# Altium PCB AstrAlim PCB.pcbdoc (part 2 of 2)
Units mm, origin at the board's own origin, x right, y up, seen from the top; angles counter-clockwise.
Board outline 123.28 x 79.48 mm, 4 copper layers (Top Layer, Inner1, Inner2, Bottom Layer); 156 components, 74 nets, 482 pads, 222 vias.
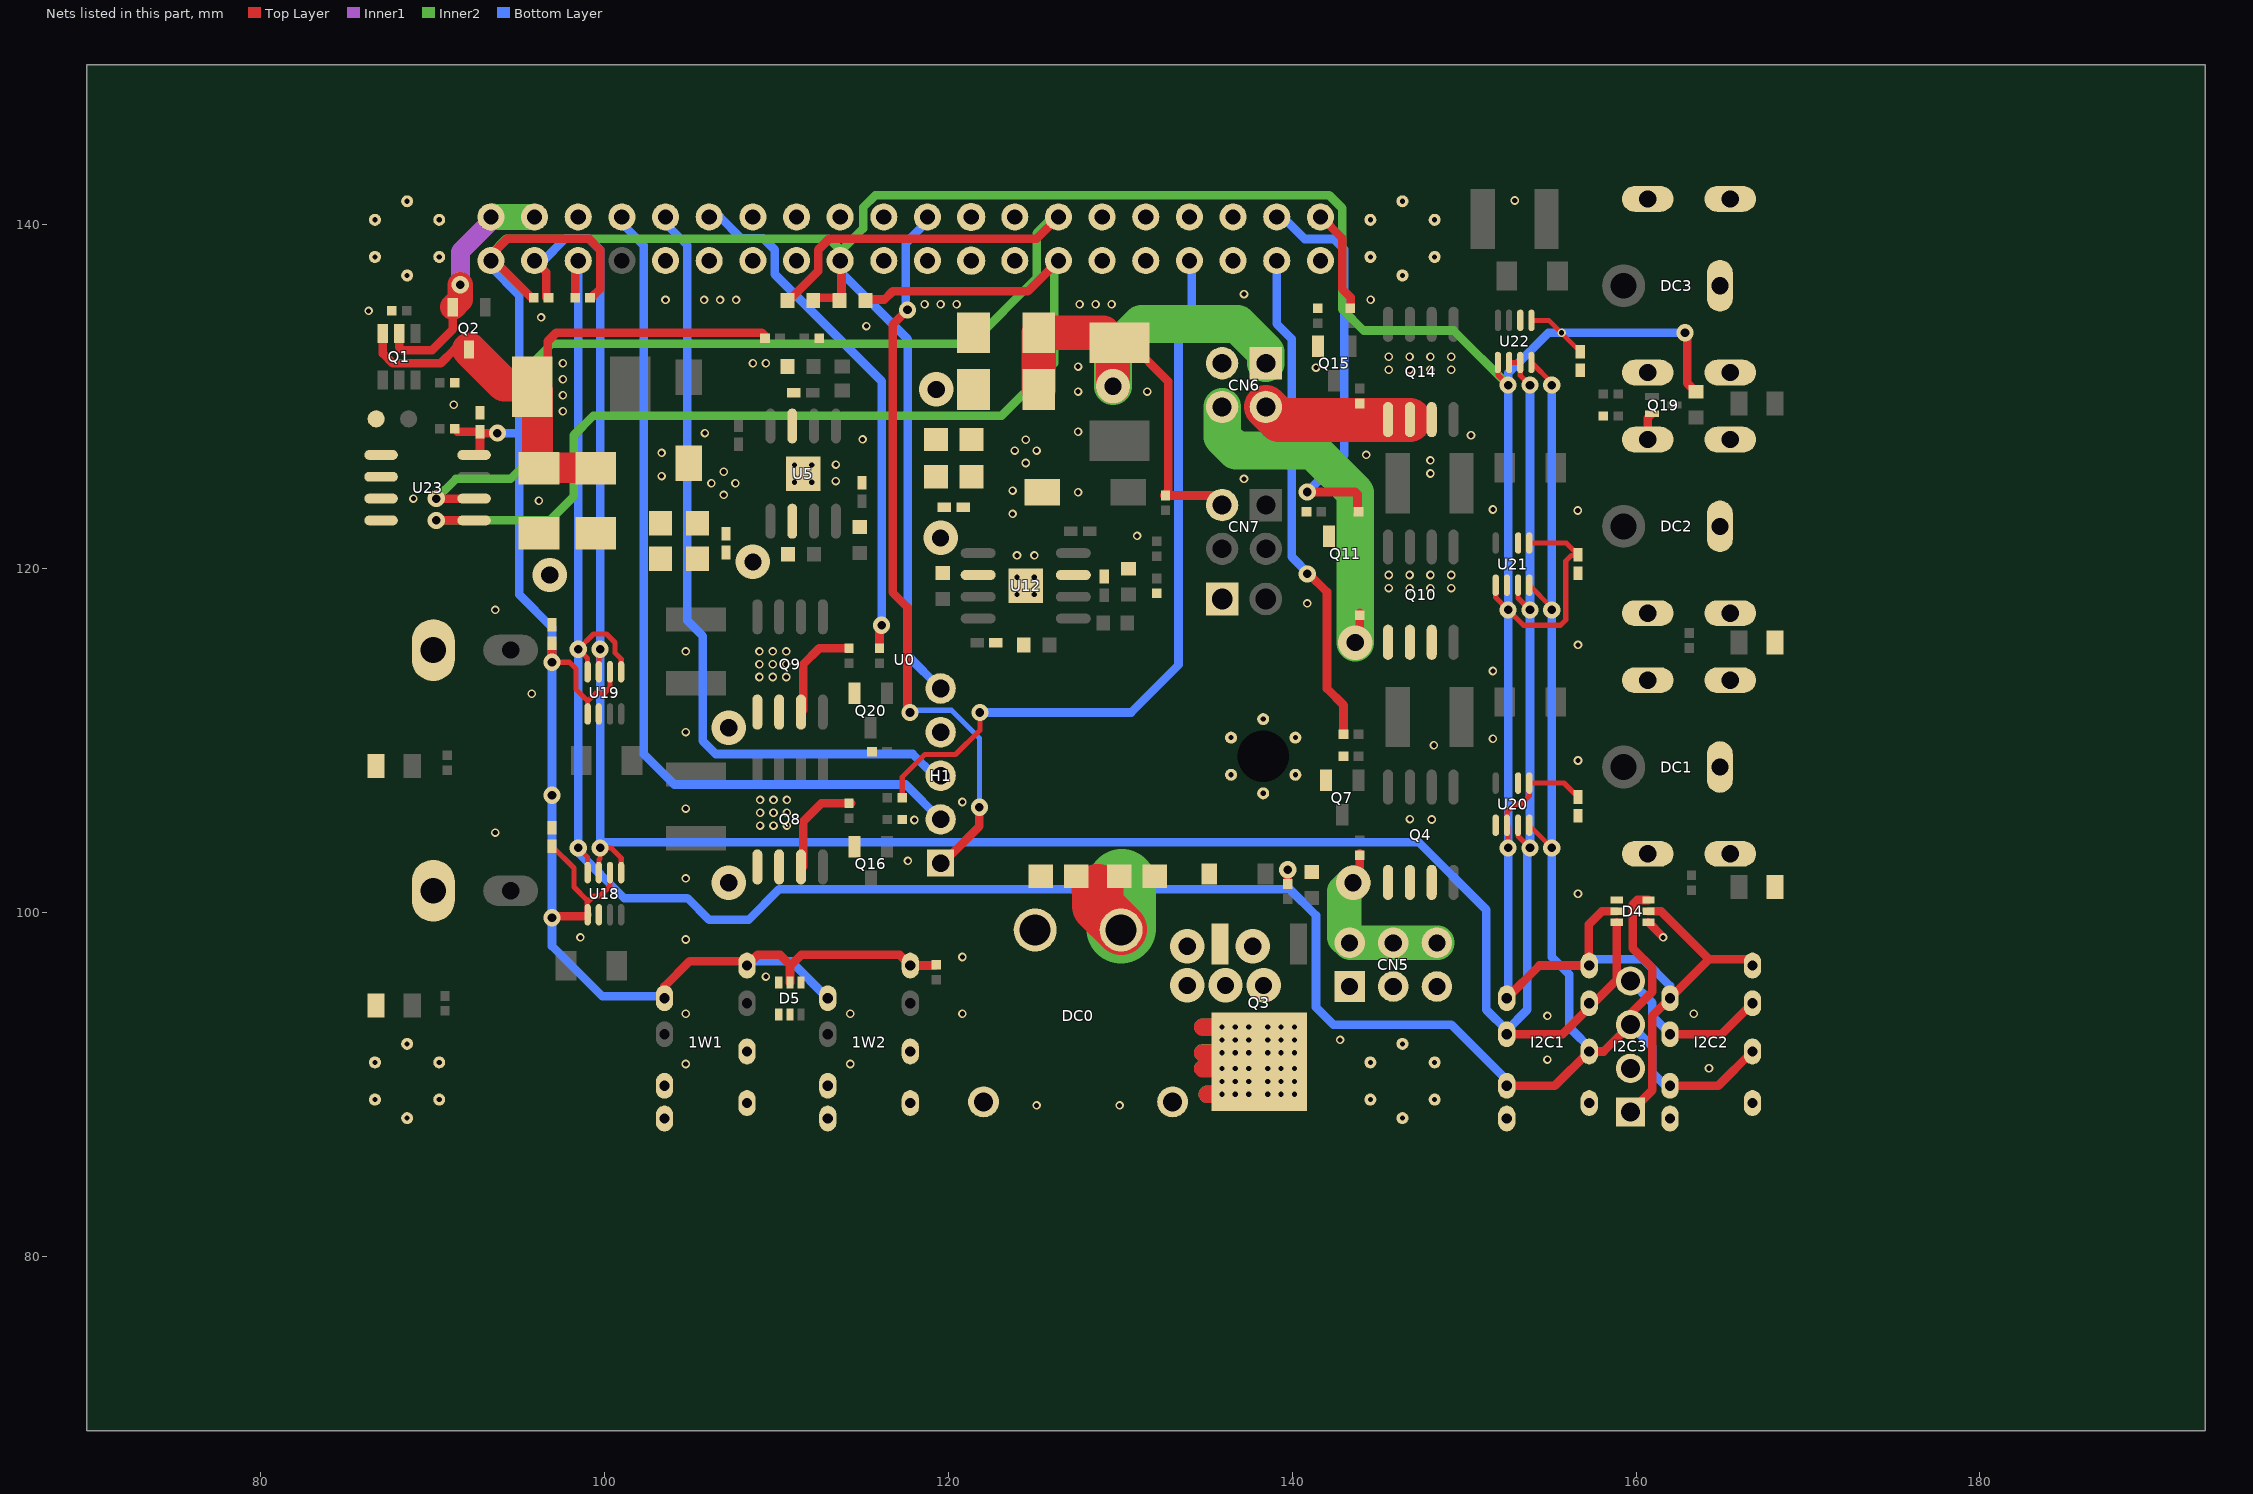
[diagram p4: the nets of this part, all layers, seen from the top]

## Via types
v1: diameter 0.5, hole 0.3, Top Layer to Bottom Layer, 164 vias
v2: diameter 1, hole 0.5, Top Layer to Bottom Layer, 30 vias
v3: diameter 2, hole 1, Top Layer to Bottom Layer, 14 vias
v4: diameter 0.61, hole 0.305, Top Layer to Bottom Layer, 8 vias
v5: diameter 0.8, hole 0.4, Top Layer to Bottom Layer, 6 vias

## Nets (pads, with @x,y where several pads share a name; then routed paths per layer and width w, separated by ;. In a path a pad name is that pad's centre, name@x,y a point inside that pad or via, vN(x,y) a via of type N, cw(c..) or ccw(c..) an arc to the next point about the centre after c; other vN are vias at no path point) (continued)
+3.3V: 1W1.4 1W1.8 1W2.4 1W2.8 C16.1 C19.1 C20.1 C30.1 C32.1 C38.2 D4.2 D4.5 D5.5 H1.5 I2C1.4 I2C1.8 I2C2.4 I2C2.8 I2C3.1 R6.2 R7.2 R19.2 R88.1 R89.2 R90.2 R91.2 U0.1 U0.17 U18.2 U18.5 U19.2 U19.5 U20.2 U20.5 U21.1 U21.5 U22.1 U22.5 U23.8 | length 324.2
  Top Layer w0.3: C19.1@96.933,103.849 98.203,102.579 98.203,101.473 98.965,100.711 98.965,100.584 ; v2(96.933,114.554) 97.949,114.554 98.33,114.173 98.33,112.985 99.006,112.309 ; U18.5@98.965,99.825 98.965,100.584 ; U19.5@99.006,111.55 99.006,112.309 ; U18.2@100.306,102.318 100.306,101.544 99.727,100.965 99.346,100.965 98.965,100.584 ; U19.2@100.306,114.002 100.306,113.101 99.981,112.776 99.473,112.776 99.006,112.309 ; U21.1@151.838,119.043 151.838,118.323 v2(152.559,117.602) 153.448,116.713 155.607,116.713 155.907,117.013 155.907,120.442 156.242,120.777 156.586,120.777 C30.1@156.623,120.814 155.942,121.495 U21.5@153.788,121.495 ; U22.1@151.965,131.997 151.965,131.277 v2(152.559,130.683) ; v2(152.559,103.759) 152.559,105.002 U20.2@152.488,105.073 152.488,105.847 152.94,106.299 153.321,106.299 153.788,106.766 U20.5@153.788,107.525 155.815,107.525 C16.1@156.623,106.717 ; U22.5@153.915,134.449 154.926,134.449 C32.1@156.75,132.625
  Top Layer w0.5: R91.2@91.27,128.143 91.434,127.979 C38.2@92.742,127.979 ; U23.8@92.145,126.619 92.488,126.619 92.742,126.873 C38.2@92.742,127.979 ; v2(93.758,127.889) 92.832,127.889 C38.2@92.742,127.979 ; R6.2@95.738,135.763 93.579,137.922 U0.1@93.377,137.922 93.377,138.242 94.327,139.192 99.084,139.192 99.727,138.549 99.727,136.271 99.219,135.763 R7.2@99.144,135.763 ; v2(96.933,99.695) 97.018,99.78 98.965,99.78 98.965,99.825 U18.5@99.006,99.866 ; v2(96.933,114.554) C20.1@96.933,115.66 ; 1W1.8@103.477,95.012 103.477,95.698 104.934,97.155 108.034,97.155 1W1.4@108.277,96.912 108.901,97.536 110.194,97.536 110.818,96.912 ; D5.5@110.776,95.916 110.776,96.87 110.818,96.912 ; R90.2@112.479,135.763 113.772,135.763 113.772,137.847 U0.17@113.697,137.922 ; R19.2@119.285,96.953 119.244,96.912 1W2.4@117.777,96.912 117.153,97.536 111.442,97.536 110.818,96.912 ; I2C1.8@152.477,95.012 154.377,96.912 I2C1.4@157.277,96.912 157.258,96.931 157.258,99.314 158.02,100.076 D4.5@158.878,100.076 ; I2C3.1@159.671,88.392 160.941,89.662 160.941,93.976 I2C2.8@161.977,95.012 164.247,97.282 ; D4.2@160.718,100.076 161.453,100.076 164.247,97.282 ; v2(162.846,133.731) 162.981,133.596 162.981,130.793 R88.1@163.481,130.293 ; I2C2.4@166.777,96.912 166.407,97.282 164.247,97.282
  Inner2 w0.5: U0.1@93.377,137.922 93.377,138.303 94.266,139.192 113.062,139.192 113.697,138.557 U0.17@113.697,138.459 ; U0.17@113.697,137.922 U0.17@113.697,138.459 ; v2(152.559,130.683) 149.384,133.858 144.148,133.858 142.907,135.099 142.907,140.97 142.145,141.732 115.75,141.732 115.033,141.015 115.033,139.794 U0.17@113.697,138.459
  Bottom Layer w0.5: U0.1@93.377,137.922 93.377,137.545 95.028,135.894 95.028,127.909 ; v2(93.758,127.889) 95.008,127.889 95.028,127.909 ; 1W1.8@103.423,95.517 103.423,95.133 99.844,95.133 96.933,98.044 v2(96.933,99.695) v2(96.933,106.823) v2(96.933,114.554) 96.933,116.586 95.028,118.491 95.028,127.909 ; 1W1.4@108.277,96.912 108.52,97.155 110.834,97.155 1W2.8@112.977,95.012 ; U0.17@113.697,137.922 113.697,137.287 117.634,133.35 117.634,114.935 H1.5@119.539,113.03 ; I2C1.8@152.559,95.43 v2(152.559,103.759) v2(152.559,117.602) v2(152.559,130.683) 152.559,131.39 154.9,133.731 v1(155.667,133.731) v2(162.846,133.731) ; I2C1.4@157.277,96.912 157.647,97.282 160.414,97.282 161.977,95.719 I2C2.8@161.977,95.012
+5V_A: C10.1 C11.1 Q1.6 Q2.3 R14.2 U6.2 | length 34.4
  Top Layer w0.5: Q1.6@87.093,133.684 87.093,132.522 87.662,131.953 90.456,131.953 91.253,132.75 Q2.3@92.107,132.75 ; U6.2@95.79,130.714 96.679,131.603 96.679,133.231 97.179,133.731 109.137,133.731 109.327,133.541 R14.2@109.327,133.413
  Top Layer w1.8: U6.2@95.79,130.714 96.1,130.404 96.1,125.902 96.129,125.873 C11.1@98.382,125.873
  Top Layer w2: Q2.3@92.107,132.75 94.143,130.714 U6.2@95.79,130.714
+5V_PI: Q1.5 Q2.2 U0.2 U0.4 | length 14.6
  Top Layer w0.5: Q1.5@88.043,133.684 88.043,132.88 88.208,132.715 89.948,132.715 91.157,133.924 Q2.2@91.157,135.22
  Top Layer w1.5: Q2.2@91.157,135.22 91.599,135.662 v2(91.599,136.525)
  Inner1 w1.1: v2@91.599,136.652 91.599,138.43 93.377,140.208 U0.2@93.377,140.589
  Inner2 w1.3: U0.2@93.504,140.462 U0.2@93.504,140.589
  Inner2 w1.5: U0.2@93.377,140.462 93.504,140.462 U0.4@95.917,140.462
+9V: C26.1 C27.1 CN6.1 CN7.3 R67.2 U13.2 | length 37.7
  Top Layer w0.5: U13.2@129.572,133.152 130.532,133.152 132.787,130.897 132.787,124.5 R67.2@132.545,124.258 ; R67.2@132.62,124.258 135.362,124.258 CN7.3@135.922,123.698
  Top Layer w2: C27.1@125.248,130.429 C26.1@125.248,133.731 128.993,133.731 129.572,133.152 v3(129.572,130.611)
  Inner2 w2.2: v3(129.572,130.611) 129.572,132.588 131.223,134.239 136.811,134.239 138.462,132.588 CN6.1@138.462,131.953
+12V: C5.2 C6.2 C7.2 C21.2 C22.2 C23.2 C34.2 C35.2 CN5.2 CN5.4 CN5.6 CN6.4 DC0.2 Q4.1 Q4.2 Q4.3 Q8.1 Q8.2 Q8.3 Q9.1 Q9.2 Q9.3 Q10.1 Q10.2 Q10.3 R10.2 R17.1 R22.2 R27.2 R30.2 R32.2 R42.2 U5.2 U12.2 | length 50.3
  Top Layer w0.5: Q9.3@111.418,111.654 111.538,111.774 111.538,114.427 112.479,115.368 R30.2@114.205,115.368 ; Q8.3@111.545,102.648 111.545,105.29 112.606,106.351 R27.2@114.332,106.351 ; R17.1@139.732,101.652 v2(139.732,102.489) ; v3(143.542,101.727) 143.923,102.108 R22.2@143.923,103.453 ; v3(143.669,115.697) 143.923,115.951 R42.2@143.923,117.423
  Top Layer w3: 128.667,101.325 128.683,101.31 128.683,100.377 DC0.2@130.04,99.02
  Inner2 w2: v3(143.542,101.727) 143.034,101.219 143.034,98.565 143.367,98.232 CN5.4@145.877,98.232 CN5.6@148.447,98.232
  Inner2 w2.2: CN6.4@135.922,129.413 135.922,127.676 136.725,126.873 141.215,126.873 143.669,124.419 v3(143.669,115.697)
  Inner2 w4: DC0.2@130.04,99.02 130.08,99.06 130.08,101.68
  other v1: 109.036,105.056 109.816,105.056 110.596,105.056 109.036,105.802 109.816,105.802 110.596,105.802 109.036,106.548 109.816,106.548 110.596,106.548 108.998,113.697 109.778,113.697 110.558,113.697 108.998,114.443 109.778,114.443 110.558,114.443 108.998,115.189 109.778,115.189 110.558,115.189
  other v3: 107.22,101.727 107.22,110.744 108.617,120.396 119.539,121.793
GND: 1W1.1 1W1.5 1W2.1 1W2.5 C5.1 C6.1 C7.1 C8.1 C10.2 C11.2 C13.1 C16.2 C19.2 C20.2 C21.1 C22.1 C23.1 C24.1 C26.2 C27.2 C29.1 C30.2 C32.2 C34.1 C35.1 C38.1 CN5.1 CN5.3 CN5.5 CN8.1 D1.1 D2.2 D3.1 D4.1 D4.4 D5.4 DC1.2 DC1.3 DC2.2 DC2.3 DC3.2 DC3.3 GN0.1 H1.4 I2C1.1 I2C1.5 I2C2.1 I2C2.5 I2C3.2 LED1.2 LED2.2 LED4.2 LED5.2 pad.42 pad.44 pad.46 pad.48 pad.50 pad.52 PWM1.1 PWM2.1 Q3.3 Q7.2 Q11.2 Q15.2 Q16.2 Q19.2 Q20.2 R11.1 R12.2 R13.1 R16.1 R18.1 R20.1 R33.1 R34.2 R39.1 R40.1 R48.1 R54.1 R56.1 R59.1 R87.1 U0.6 U0.9 U0.14 U0.20 U0.25 U0.30 U0.34 U0.39 U0.42 U0.44 U0.46 U0.48 U0.50 U0.52 U5.7 U5.9 U12.7 U12.9 U18.6 U19.6 U20.1 U20.6 U21.2 U21.6 U22.6 U23.3 U23.4 | length 2.8
  Top Layer w0.5: DC2.2@160.677,127.512 160.677,128.768 Q19.2@160.926,129.017 ; D4.1@160.718,99.426 161.576,98.568 v1(161.576,98.552)
  other v1: 125.127,88.773 129.953,88.773 164.243,90.932 104.712,91.186 114.283,91.186 154.845,91.44 142.78,92.583 154.845,93.98 104.712,94.107 114.283,94.107 120.809,94.107 163.354,94.107 109.379,96.266 120.809,97.409 104.712,98.425 98.584,98.552 156.623,101.092 104.712,101.981 117.634,102.997 93.631,104.648 118.015,105.378 148.114,105.41 146.844,105.429 104.712,106.045 120.809,106.426 156.623,108.839 148.241,109.728 151.67,110.109 104.712,110.49 95.754,112.725 151.67,114.046 104.712,115.189 156.623,115.57 93.631,117.602 140.875,117.983 145.614,118.872 146.826,118.872 148.033,118.872 149.249,118.872 145.614,119.634 146.826,119.634 148.033,119.634 149.249,119.634 123.984,120.777 125,120.777 130.969,121.91 123.73,123.19 156.613,123.384 151.67,123.444 96.171,123.952 88.869,124.079 106.921,124.292 127.543,124.451 123.73,124.542 106.204,124.968 107.601,124.968 113.443,125.095 137.192,125.222 103.312,125.39 148.033,125.54 106.921,125.644 113.451,126.057 124.492,126.148 148.033,126.302 144.304,126.619 103.312,126.74 123.857,126.873 125.127,126.873 124.492,127.5 115.004,127.524 150.4,127.762 105.823,127.889 127.543,127.971 97.568,129.159 91.218,129.54 97.568,130.09 127.543,130.302 131.564,130.302 97.568,131.022 145.614,131.572 146.826,131.572 148.033,131.572 149.249,131.572 141.383,131.699 127.543,131.76 97.568,131.953 108.617,131.953 109.379,131.953 145.614,132.334 146.826,132.334 148.033,132.334 149.249,132.334 115.221,134.112 96.298,134.62 86.265,135.001 118.608,135.382 119.539,135.382 120.47,135.382 127.625,135.382 128.556,135.382 129.487,135.382 103.537,135.636 105.781,135.636 106.712,135.636 107.643,135.636 144.558,135.651 137.192,135.978 152.94,141.424
  other v3: 133.89,95.758 136.112,95.758 138.335,95.758 133.89,98.034 137.7,98.034 96.806,119.634 119.285,130.429
GND_IN: DC0.1 Q3.2 | length 8.5
  Top Layer w1: 134.778,90.906 Q3.2@135.778,90.906 ; 134.778,91.828 Q3.2@135.778,91.828 ; 134.778,93.319 Q3.2@135.778,93.319 ; 135.032,89.415 Q3.2@136.032,89.415
  Inner2 w1: 134.777,90.916 v1(135.904,90.916) ; 134.777,91.837 v1(135.904,91.837) ; 134.777,93.329 v1(135.904,93.329) ; 135.031,89.424 v1(135.904,89.424) 136.158,89.424
  other v1: 136.684,89.424 137.464,89.424 138.571,89.424 139.351,89.424 140.131,89.424 135.904,90.17 136.684,90.17 137.464,90.17 138.571,90.17 139.351,90.17 140.131,90.17 136.684,90.916 137.464,90.916 138.571,90.916 139.351,90.916 140.131,90.916 136.684,91.837 137.464,91.837 138.571,91.837 139.351,91.837 140.131,91.837 135.904,92.583 136.684,92.583 137.464,92.583 138.571,92.583 139.351,92.583 140.131,92.583 136.684,93.329 137.464,93.329 138.571,93.329 139.351,93.329 140.131,93.329
GPIO13_PWM1: R53.1 U0.33 | length 44.5
  Top Layer w0.3: R53.1@117.305,106.68 117.305,107.875 118.623,109.193 120.415,109.193 121.825,110.603 v2(121.825,111.633)
  Bottom Layer w0.5: v2(121.825,111.633) 130.615,111.633 133.382,114.4 133.382,133.35 134.144,134.112 U0.33@134.144,137.992
GPIO18_PWM0: R55.1 U0.12 | length 30.4
  Top Layer w0.5: R55.1@115.983,115.368 115.983,116.586 v2(116.11,116.713)
  Bottom Layer w0.5: U0.12@106.077,140.462 106.704,140.462 107.935,139.231 109.213,139.231 109.887,138.557 109.887,137.127 116.11,130.904 v2(116.11,116.713)
GPIO20: R41.1 U0.38 | length 23.7
  Top Layer w0.5: v2(140.875,124.46) 143.669,124.46 143.796,124.333 143.796,123.369 R41.1@143.848,123.317
  Bottom Layer w0.5: U0.38@139.12,140.38 139.53,140.38 140.729,139.181 142.41,139.181 143.017,138.574 143.017,126.602 v2(140.875,124.46)
GPIO21: R49.1 U0.40 | length 6
  Top Layer w0.5: U0.40@141.694,140.442 142.9,139.236 142.9,136.284 143.395,135.79 R49.1@143.395,135.156
GPIO26: R21.1 U0.37 | length 29.2
  Top Layer w0.5: v2@140.964,119.698 142.018,118.644 142.018,113.03 142.992,112.056 142.982,112.046 R21.1@142.982,110.363
  Bottom Layer w0.5: U0.37@139.097,137.922 139.097,134.239 139.973,133.363 139.973,120.689 v2@140.964,119.698
  other v2: 140.875,119.698
ID_SC: R90.1 U0.28 U23.6 | length 68.1
  Top Layer w0.5: v2(90.202,124.079) U23.6@92.145,124.079 ; R90.1@110.632,135.714 110.822,135.714 112.427,137.319 112.427,138.557 113.062,139.192 125.127,139.192 U0.28@126.397,140.462
  Inner2 w0.5: v2(90.202,124.079) 91.345,125.222 94.52,125.222 95.79,126.492 95.79,131.953 96.933,133.096 121.317,133.096 125.127,136.906 125.127,139.524 126.065,140.462 U0.28@126.397,140.462
ID_SD: R89.1 U0.27 U23.5 | length 61.9
  Top Layer w0.5: v2(90.202,122.809) U23.5@92.145,122.809 ; R89.1@115.231,135.66 116.269,135.66 116.752,136.144 ; 116.756,136.148 116.752,136.144 ; U0.27@126.397,137.922 124.619,136.144 116.752,136.144
  Inner2 w0.5: v2(90.202,122.809) 96.806,122.809 98.203,124.206 98.203,127.762 99.346,128.905 123.095,128.905 126.143,131.953 126.143,137.668 U0.27@126.397,137.922
PPS: H1.1 U0.22 | length 43.5
  Top Layer w0.5: v2(117.761,111.633) 117.614,111.78 117.614,117.749 116.745,118.618 116.745,134.19 v2(117.614,135.059) v2@117.761,134.912 ; H1.1@119.503,102.719 121.798,105.014 v2(121.798,106.125)
  Bottom Layer w0.3: v2(117.761,111.633) 117.89,111.762 120.172,111.762 121.798,110.136 v2@121.798,106.18
  Bottom Layer w0.5: v2(117.614,135.059) 117.507,135.166 117.507,138.938 118.777,140.208 U0.22@118.777,140.462
RXD: H1.3 U0.10 | length 46.1
  Bottom Layer w0.5: U0.10@103.537,140.462 103.537,140.081 104.807,138.811 104.807,116.967 105.696,116.078 105.696,109.982 106.458,109.22 117.911,109.22 119.181,107.95 H1.3@119.539,107.95
SCL: D4.3 I2C1.2 I2C1.6 I2C2.2 I2C2.6 I2C3.3 R7.1 U0.5 U18.4 U19.1 U19.4 U20.4 U21.4 U22.4 | length 182.5
  Top Layer w0.3: v2(98.457,103.759) 99.006,103.21 U18.4@99.006,102.318 ; U19.4@99.006,114.002 99.006,114.767 v2(98.457,115.316) 99.346,116.205 100.108,116.205 100.603,115.71 100.603,115.104 100.956,114.751 U19.1@100.956,114.002 ; U20.4@153.788,105.073 155.099,103.762 v2(155.099,103.759) ; U21.4@153.788,119.043 155.099,117.732 v2(155.099,117.602) ; U22.4@153.915,131.997 155.099,130.813 v2(155.099,130.683)
  Top Layer w0.5: R7.1@98.278,135.763 98.278,137.743 U0.5@98.457,137.922 ; I2C1.6@152.477,89.912 155.277,89.912 I2C1.2@157.277,91.912 158.111,91.912 I2C3.3@159.671,93.472 159.671,94.107 160.941,95.377 160.941,96.774 159.798,97.917 159.798,100.457 160.067,100.726 D4.3@160.718,100.726 ; I2C2.6@161.977,89.912 164.777,89.912 I2C2.2@166.777,91.912
  Bottom Layer w0.5: U0.5@98.457,137.922 v2(98.457,115.316) v2(98.457,103.759) 98.457,103.505 101.124,100.838 104.807,100.838 106.077,99.568 108.363,99.568 110.141,101.346 139.859,101.346 141.383,99.822 141.383,94.488 142.399,93.472 149.257,93.472 I2C1.6@152.754,89.975 ; I2C1.6@152.563,89.912 I2C1.6@152.723,89.912 ; v2(155.099,130.683) v2(155.099,117.602) v2(155.099,103.759) 155.099,97.409 156.115,96.393 156.115,93.32 I2C1.2@157.523,91.912 ; I2C3.3@159.671,93.472 160.941,92.202 160.941,90.678 161.707,89.912 I2C2.6@161.977,89.912
SDA: D4.6 I2C1.3 I2C1.7 I2C2.3 I2C2.7 I2C3.4 R6.1 U0.3 U18.1 U18.3 U19.3 U20.3 U21.3 U22.2 U22.3 | length 172.7
  Top Layer w0.3: U18.3@99.656,102.318 99.656,103.067 99.727,103.138 v2(99.727,103.759) 100.362,103.759 100.956,103.165 U18.1@100.956,102.318 ; U19.3@99.656,114.002 99.656,114.751 99.727,114.822 v2(99.727,115.316) ; U22.2@152.615,131.997 U22.3@153.265,131.997 153.265,131.247 v2(153.829,130.683) ; U20.3@153.138,105.073 153.138,104.45 v2(153.829,103.759) ; U21.3@153.138,119.043 153.138,118.293 v2(153.829,117.602)
  Top Layer w0.5: U0.3@95.917,137.922 96.604,137.235 R6.1@96.604,135.763 ; I2C1.7@152.723,92.912 155.723,92.912 158.823,96.012 I2C3.4@158.878,96.012 ; D4.6@158.878,99.426 I2C3.4@158.878,96.012 ; I2C3.4@159.671,96.012 I2C3.4@158.878,96.012 ; I2C2.7@161.977,92.912 164.977,92.912 I2C2.3@166.777,94.712
  Bottom Layer w0.5: U0.3@95.917,137.922 96.425,137.922 97.695,139.192 99.092,139.192 99.727,138.557 v2(99.727,115.316) v2(99.727,103.759) 100.061,104.093 147.35,104.093 151.289,100.155 151.289,94.346 152.488,93.147 153.677,94.336 153.677,103.607 v2(153.829,103.759) v2(153.829,117.602) v2(153.829,130.683) ; I2C3.4@159.671,96.012 160.941,94.742 160.941,93.98 161.977,92.944 I2C2.7@161.977,92.912
TXD: H1.2 U0.8 | length 50.6
  Bottom Layer w0.5: U0.8@100.997,140.462 100.997,140.081 102.267,138.811 102.267,109.22 104.045,107.442 117.507,107.442 H1.2@119.539,105.41
VS: CN6.2 Q14.1 Q14.2 Q14.3 R50.2 | length 8.7
  Top Layer w2.54: CN6.2@138.462,129.413 139.224,128.651 146.822,128.651 Q14.2@146.844,128.673
"": 1W1.2 1W1.6 1W2.2 1W2.6 CN6.3 D5.1 D5.2 D5.6 DC0.3 DC0.4 pad.41 U0.11 U0.13 U0.15 U0.16 U0.18 U0.19 U0.21 U0.23 U0.24 U0.26 U0.29 U0.31 U0.32 U0.35 U0.36 U23.1 U23.2
  other v4: 123.992,118.499 124.992,118.499 123.992,119.499 124.992,119.499 111.046,125.031 112.046,125.031 111.046,126.031 112.046,126.031

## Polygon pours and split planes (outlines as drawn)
GND on Top Layer (solid, remove dead copper, pour order 0): 84.868,86.614 170.213,86.614 170.213,142.875 84.868,142.875
GND on Bottom Layer (solid, remove dead copper, pour order 1): 84.868,86.614 170.235,86.614 170.235,142.875 84.868,142.875
GND on Inner1 (solid, remove dead copper, pour order 2): 84.868,86.614 170.213,86.614 170.213,142.875 84.868,142.875
GND on Inner2 (solid, remove dead copper, pour order 3): 84.868,86.614 170.213,86.614 170.213,142.875 84.868,142.875

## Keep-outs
Top Layer:
  region net "": 101.05,107.569 ccw(c100.87,107.566) 100.69,107.569 ccw(c100.87,107.572)
  region net "": 155.592,138.091 155.76,138.091 155.76,138.367 155.592,138.367
Bottom Layer:
  region net "": 152.048,100.39 ccw(c151.905,100.39) 151.762,100.39 ccw(c151.905,100.391)
  region net "": 100.202,108.235 100.588,108.235 100.588,110.737 100.202,110.737
  region net "": 103.602,106.656 103.988,106.656 103.988,106.987 103.602,106.987
  region net "": 97.568,115.189 97.158,114.779 97.158,114.776 97.507,114.427 97.8,114.427 97.8,114.957
  region net "": 97.432,102.715 97.695,103.124 98.076,103.124 97.822,102.87
  region net "": 97.441,102.87 97.695,103.124 98.076,103.124 97.822,102.87

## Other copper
Top Layer:
  region net +12V: 126.651,101.483 130.719,101.483 130.719,102.87 126.651,102.87
  region net +12V: 108.109,119.38 107.728,119.761 103.797,119.761 103.785,119.761 102.521,119.753 102.521,121.412 110.052,121.412 110.522,121.882 110.522,123.758 110.774,124.01 111.026,124.01 111.319,123.717 111.319,120.05 110.649,119.38
  region net +12V: 119.14,119.271 118.591,119.82 118.526,119.918 118.513,119.949 118.49,120.064 118.49,128.062 118.578,128.274 118.602,128.298 118.814,128.386 119.85,128.386 120.062,128.298 120.145,128.215 120.233,128.003 120.233,123.274 120.446,121.767 120.341,120.707 120.449,120.407 120.836,120.103 120.901,120.065 120.956,120.04 121.076,120.015 122.444,120.015 122.559,119.992 122.59,119.979 122.688,119.914 122.74,119.862 122.805,119.764 122.818,119.733 122.841,119.618 122.841,119.567 122.818,119.452 122.805,119.421 122.74,119.323 122.688,119.271 122.59,119.206 122.559,119.193 122.444,119.17 119.383,119.17 119.269,119.193 119.237,119.206
  region net +12V: 143.669,114.576 cw(c143.669,115.719) 142.526,115.719 cw(c143.669,115.719) 143.669,116.862 148.422,116.862 148.622,116.662 148.622,114.776 148.422,114.576
  region net +12V: 143.542,100.584 cw(c143.542,101.727) 142.399,101.727 cw(c143.542,101.727) 143.542,102.87 148.295,102.87 148.495,102.67 148.495,100.784 148.295,100.584
  region net +12V: 106.629,111.532 108.296,112.351 108.307,112.358 108.909,112.759 108.965,112.776 111.692,112.776 111.792,112.676 111.792,110.586 111.692,110.486 108.4,110.486 108.33,110.457 107.926,110.053 107.784,110.053 106.602,111.235 106.573,111.306 106.573,111.442
  region net +12V: 106.629,102.524 108.296,103.343 108.307,103.35 108.909,103.752 108.965,103.768 111.692,103.768 111.792,103.668 111.792,101.578 111.692,101.478 108.4,101.478 108.33,101.449 107.926,101.045 107.784,101.045 106.602,102.227 106.573,102.298 106.573,102.434
  region net $2N3430: 145.393,120.269 149.438,120.269 149.638,120.469 149.638,122.101 149.438,122.301 145.393,122.301 145.193,122.101 145.193,120.469
  region net VS: 146.79,127.381 148.332,127.381 148.532,127.581 148.532,129.724 148.332,129.924 146.79,129.924 146.59,129.724 146.59,127.581
  region net $2N538: 145.139,106.299 149.692,106.299 149.892,106.499 149.892,108.131 149.692,108.331 145.139,108.331 144.939,108.131 144.939,106.499
  region net $2N1618: 103.737,116.078 112.735,116.078 112.935,116.278 112.935,118.037 112.735,118.237 103.737,118.237 103.537,118.037 103.537,116.278
  region net $2N1605: 103.835,107.154 103.693,107.295 103.664,107.366 103.664,108.739 103.764,108.839 107.705,108.839 107.749,108.849 108.633,109.274 108.677,109.283 112.821,109.283 112.891,109.254 113.033,109.113 113.062,109.042 113.062,107.366 113.033,107.295 112.891,107.154 112.821,107.124 103.905,107.124
  region net $2N4466: 145.393,133.223 145.193,133.423 145.193,135.055 145.393,135.255 148.214,135.255 148.422,135.255 149.665,135.255 149.765,135.155 149.765,133.323 149.665,133.223 148.422,133.223 148.214,133.223
  region net $1N14596: 126.143,120.723 126.143,121.212 126.343,121.412 127.594,121.412 127.794,121.612 127.794,122.853 127.853,122.995 129.259,124.401 129.318,124.543 129.318,126.927 129.518,127.127 131.023,127.127 131.223,126.927 131.223,123.527 131.164,123.385 128.361,120.582 128.219,120.523 126.343,120.523
  region net $1N4920: 110.014,127.454 109.814,127.254 109.208,127.254 109.066,127.313 108.418,127.961 108.277,128.019 107.486,128.019 107.286,128.219 107.286,128.248 105.867,129.667 102.267,129.667 102.267,132.207 104.909,132.207 105.925,132.207 107.264,132.207 107.406,132.148 109.955,129.599 110.014,129.457
  region net +5V_A: 93.377,130.048 95.478,127.947 96.498,127.947 96.498,130.007 96.1,130.404 93.733,130.404
  region net +5V_A: 94.647,132.334 93.758,132.334 94.692,131.399 95.028,131.399 95.028,131.953
  region net $1N59627: 126.506,114.173 126.506,114.462 126.206,114.762 125.528,114.762 125.228,114.462 125.228,114.173 125.528,113.873 126.206,113.873
  region net $2N3428: 152.96,126.697 152.95,126.697 152.95,126.708
  region net $2N3428: 152.95,126.697 150.14,126.697 149.72,126.276 149.72,124.067 150.498,123.288 152.255,125.045 152.95,125.045
  region net $2N40244: 154.728,126.865 157.568,126.865 157.663,126.771 157.663,124.951 157.463,124.751 154.728,124.751 154.728,126.844 154.738,126.855
  region net GND_IN: 134.987,93.924 134.987,88.894 134.681,88.894 134.525,89.665 134.437,89.877 133.851,90.463 133.639,90.551 128.936,90.551 128.724,90.639 123.555,95.807 123.468,96.019 123.468,99.02 123.47,99.02 cw(c125.04,99.02) 125.04,100.59 cw(c125.04,99.02) 126.61,99.02 126.61,97.955 126.698,97.743 128.458,95.983 128.67,95.895 131.788,95.895 132,95.807 133.485,94.322 133.697,94.234
Inner2:
  region net GND_IN: 135.638,88.924 140.568,88.924 140.568,93.816 135.638,93.816
  region net +12V: 122.173,98.771 121.982,98.733 108.419,98.733 108.228,98.771 108.058,98.842 107.896,98.95 105.85,100.996 105.742,101.158 105.671,101.328 105.633,101.52 105.633,119.831 105.671,120.023 105.742,120.192 105.85,120.355 107.214,121.719 107.376,121.827 107.546,121.897 107.737,121.935 108.568,121.935 108.759,121.973 108.929,122.044 109.091,122.152 110.178,123.239 110.3,123.239 110.3,123.249 119.517,123.249 119.708,123.211 119.878,123.141 120.04,123.032 121.304,121.768 121.412,121.606 121.482,121.436 121.52,121.245 121.52,119.36 121.558,119.168 121.629,118.998 121.737,118.836 123.52,117.054 123.682,116.945 123.852,116.875 124.043,116.837 144.221,116.837 144.413,116.799 144.582,116.729 144.745,116.62 145.065,116.299 145.174,116.137 145.244,115.967 145.282,115.776 145.282,101.727 145.244,101.535 145.174,101.366 145.065,101.203 144.037,100.175 143.875,100.067 143.816,100.043 143.654,99.934 143.561,99.841 143.208,99.695 134.217,99.695 133.864,99.841 132.679,101.026 132.325,101.173 124.935,101.173 124.319,100.918
  region net GND_IN: 134.987,93.924 134.987,88.903 134.681,88.903 134.525,89.665 134.437,89.877 133.851,90.463 133.639,90.551 128.936,90.551 128.724,90.639 123.555,95.807 123.468,96.019 123.468,99.02 123.47,99.02 cw(c125.04,99.02) 125.04,100.59 cw(c125.04,99.02) 126.61,99.02 126.61,97.955 126.698,97.743 128.458,95.983 128.67,95.895 131.788,95.895 132,95.807 133.485,94.322 133.697,94.234
Bottom Layer:
  region net GND_IN: 135.496,88.943 140.568,88.943 140.568,93.835 135.496,93.835
  region net +3.3V: 95.335,127.373 95.335,128.261 95.135,128.461 94.667,128.461 94.467,128.261 94.467,127.373 94.667,127.173 95.135,127.173
  region net SDA: 100.387,103.726 100.387,104.361 99.933,104.815 99.719,104.815 99.519,104.615 99.519,103.726 99.719,103.526 100.187,103.526

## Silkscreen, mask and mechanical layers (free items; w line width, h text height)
Top Silkscreen Layer:
  circle w0.254 net "": c138.309,109.09 r3.101
  region net "": 93.877,107.462 ccw(c93.377,107.462) 92.877,107.462 ccw(c93.377,107.462)
  region net "": 158.877,101.462 ccw(c158.377,101.459) 157.877,101.462 ccw(c158.377,101.465)
  region net "": 143.915,113.538 ccw(c143.415,113.538) 142.915,113.538 ccw(c143.415,113.538)
  region net "": 134.39,92.583 ccw(c133.89,92.583) 133.39,92.583 ccw(c133.89,92.583)
  region net "": 111.149,99.314 ccw(c110.649,99.314) 110.149,99.314 ccw(c110.649,99.314)
  lines w0.1 net "": 142.454,94.49 142.454,94.043 142.581,93.916 144.486,93.916 ; 142.454,99.471 142.454,99.918 142.581,100.045 144.486,100.045 ; 147.164,93.916 149.069,93.916 149.196,94.043 149.196,94.49 ; 147.291,100.045 149.196,100.045 149.323,99.918 149.323,99.471
  lines w0.3 net "": 94.266,120.126 ccw(c95.266,120.126) 95.266,119.126 114.78,119.126 ccw(c114.78,120.126) 115.78,120.126 115.78,133.708 ccw(c114.78,133.708) 114.78,134.708 95.266,134.708 ccw(c95.266,133.708) 94.266,133.708 94.266,120.126 ; 117.379,115.751 ccw(c118.379,115.751) 118.379,114.751 132.763,114.751 ccw(c132.763,115.751) 133.763,115.751 133.763,135.144 ccw(c132.763,135.144) 132.763,136.144 118.379,136.144 ccw(c118.379,135.144) 117.379,135.144 117.379,115.751
  text "[mA]" at 155.483,134.308 h0.52
  text "Vs" at 136.344,133.88 h0.97
  text "Vt" at 118.088,133.667 h1.3
  text "RPi" at 105.387,133.572 h0.65
  text "5V" at 102.594,132.905 h1.3
  text "9V/5V" at 117.544,132.766 h0.52
  text "OUT3 /  [Vs]" at 157.23,128.624 h0.51 r90
  text "Vt" at 136.406,125.69 h0.97
  text "[mA]" at 156.845,116.849 h0.52 r90
  text "Disable Vt" at 134.397,116.046 h0.65
  text "OUT2 /  [12V]" at 161.929,114.48 h0.51 r90
  text "GPS /  VCC" at 121.082,112.488 h0.51
  text "[mA]" at 97.136,111.947 h0.52 r90
  text "GND" at 121.151,110.213 h0.45
  text "[12V]" at 91.735,109.495 h0.45 r270
  text "GPS /  RXD" at 121.082,107.456 h0.51
  text "GPS /  TXD" at 121.082,104.245 h0.51
  text "[mA]" at 156.845,102.8 h0.52 r90
  text "GPS /  PPS" at 121.082,102.117 h0.51
  text "[mA]" at 97.136,101.152 h0.52 r90
  text "OUT1 /  [12V]" at 162.31,100.637 h0.51 r90
  text "12V" at 145.07,99.671 h0.65
  text "GND" at 120.858,99.625 h0.91
  text "12V" at 131.526,99.625 h0.91
  text "v1.1" at 169.101,97.452 h0.65 r90
  text "[12V]" at 91.562,95.774 h0.45 r270
  text "GND" at 144.881,93.557 h0.65
  text "XT30PW-M" at 123.433,91.392 h0.97
  text "1-Wire" at 110.969,87.267 h0.97 r90
  text "I2C OUT" at 151.083,87.122 h0.97 r90
  text "DC 12V IN" at 120.349,87.036 h0.97 r90
Bottom Silkscreen Layer:
  lines w0.15 net "": 84.972,96.842 ccw(c86.472,96.842) 86.472,95.342 94.694,95.342 ccw(c94.694,96.842) 96.194,96.842 96.194,105.342 ccw(c94.694,105.342) 94.694,106.842 86.472,106.842 ccw(c86.472,105.342) 84.972,105.342 84.972,96.842 ; 84.972,110.812 ccw(c86.472,110.812) 86.472,109.312 94.694,109.312 ccw(c94.694,110.812) 96.194,110.812 96.194,119.312 ccw(c94.694,119.312) 94.694,120.812 86.472,120.812 ccw(c86.472,119.312) 84.972,119.312 84.972,110.812 ; 101.505,88.114 ccw(c103.005,88.114) 103.005,86.614 118.166,86.614 ccw(c118.166,88.114) 119.666,88.114 119.666,96.417 ccw(c118.166,96.417) 118.166,97.917 103.005,97.917 ccw(c103.005,96.417) 101.505,96.417 101.505,88.114 ; 123.179,88.2 ccw(c124.679,88.2) 124.679,86.7 130.444,86.7 ccw(c130.444,88.2) 131.944,88.2 131.944,99.338 ccw(c130.444,99.338) 130.444,100.838 124.679,100.838 ccw(c124.679,99.338) 123.179,99.338 123.179,88.2 ; 151.028,88.114 ccw(c152.528,88.114) 152.528,86.614 166.807,86.614 ccw(c166.807,88.114) 168.307,88.114 168.307,96.544 ccw(c166.807,96.544) 166.807,98.044 152.528,98.044 ccw(c152.528,96.544) 151.028,96.544 151.028,88.114 ; 157.162,103.978 ccw(c158.662,103.978) 158.662,102.478 169.662,102.478 ccw(c169.662,103.978) 171.162,103.978 171.162,113.178 ccw(c169.662,113.178) 169.662,114.678 158.662,114.678 ccw(c158.662,113.178) 157.162,113.178 157.162,103.978 ; 157.162,117.978 ccw(c158.662,117.978) 158.662,116.478 169.662,116.478 ccw(c169.662,117.978) 171.162,117.978 171.162,127.178 ccw(c169.662,127.178) 169.662,128.678 158.662,128.678 ccw(c158.662,127.178) 157.162,127.178 157.162,117.978 ; 157.162,131.724 ccw(c158.662,131.724) 158.662,130.224 169.662,130.224 ccw(c169.662,131.724) 171.162,131.724 171.162,140.924 ccw(c169.662,140.924) 169.662,142.424 158.662,142.424 ccw(c158.662,140.924) 157.162,140.924 157.162,131.724
  text "GND" at 169.051,140.467 h0.84 r90
  text "Vs" at 159.661,140.014 h0.84 r90
  text "DC3 /  OUT" at 163.517,135.495 h1.09
  text "GND" at 169.051,126.497 h0.84 r90
  text "12V" at 159.534,126.462 h0.84 r90
  text "DC2 /  OUT" at 163.549,121.295 h1.09
  text "oshwlab.com/ /  pololamag/ /  astralim" at 131.738,120.05 h0.97
  text "GND" at 92.253,114.316 h0.65 r90
  text "GND" at 169.096,112.502 h0.84 r90
  text "12V" at 159.579,112.467 h0.84 r90
  text "PWM1 /  +12V" at 94.659,111.947 h0.72
  text "DC1 /  OUT" at 163.518,107.295 h1.09
  text "v1.1" at 151.447,104.66 h0.78
  text "GND" at 92.209,100.285 h0.65 r90
  text "PWM2 /  +12V" at 94.734,97.797 h0.72
  text "3.3V" at 107.198,96.771 h0.84
  text "3.3V" at 116.763,96.717 h0.84
  text "3.3V" at 165.658,96.682 h0.84
  text "DC IN" at 129.403,95.583 h0.97
  text "SDA" at 165.695,94.142 h0.84
  text "1-W" at 107.235,93.814 h0.84
  text "1-W" at 116.8,93.761 h0.84
  text "x" at 107.307,91.787 h0.85
  text "x" at 116.872,91.734 h0.85
  text "SCL" at 165.695,91.729 h0.84
  text "GND" at 126.579,90.078 h0.84
  text "12V" at 130.262,90.078 h0.84
  text "GND" at 165.695,89.697 h0.84
  text "I2C" at 152.898,89.645 h0.97 r270
  text "GND" at 107.235,89.496 h0.84
  text "GND" at 116.8,89.443 h0.84
  text "1-Wire" at 108.635,88.749 h0.97 r270
  text "JLCJLCJLCJLC" at 98.272,87.725 h0.65
Mech6:
  circle w0.2 net "": c93.377,140.462 r0.741
  lines w0.1 net "": 136.493,83.058 138.843,89.027 141.821,97.216 ; 129.826,76.2 144.939,76.2 144.939,82.931 129.826,82.931 129.826,76.2
  lines w0.3 net "": 115.958,139.192 119.007,139.192 ; 117.507,137.667 117.507,140.717 ; 92.107,136.655 142.9,136.655 142.9,141.732 92.107,141.732 92.107,136.655 ; 102.772,86.152 108.772,86.152 108.772,99.452 102.772,99.452 102.772,86.152 ; 103.232,84.952 108.305,84.952 108.305,86.152 103.232,86.152 103.232,84.952 ; 112.272,86.152 118.272,86.152 118.272,99.452 112.272,99.452 112.272,86.152 ; 112.732,84.952 117.805,84.952 117.805,86.152 112.732,86.152 112.732,84.952 ; 120.89,87.43 134.19,87.43 134.19,90.395 120.89,90.395 120.89,87.43 ; 122.398,85.889 132.62,85.889 132.62,100.95 122.398,100.95 122.398,85.889 ; 141.948,94.422 150.028,94.422 150.028,99.502 141.948,99.502 141.948,94.422 ; 151.877,86.112 157.877,86.112 157.877,99.412 151.877,99.412 151.877,86.112 ; 152.337,84.912 157.41,84.912 157.41,86.112 152.337,86.112 152.337,84.912 ; 157.705,103.382 171.167,103.382 171.167,113.542 157.705,113.542 157.705,103.382 ; 157.705,117.382 171.167,117.382 171.167,127.542 157.705,127.542 157.705,117.382 ; 157.705,131.382 171.167,131.382 171.167,141.542 157.705,141.542 157.705,131.382 ; 161.377,86.112 167.377,86.112 167.377,99.412 161.377,99.412 161.377,86.112 ; 161.837,84.912 166.91,84.912 166.91,86.112 161.837,86.112 161.837,84.912
  text "2" at 91.218,141.277 h0.92
  text "Location ref. pin2 /  from header Pi 40p: /  => Center X = 52.5mm /  => Center Y = -43.5mm" at 130.052,77.247 h1.6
